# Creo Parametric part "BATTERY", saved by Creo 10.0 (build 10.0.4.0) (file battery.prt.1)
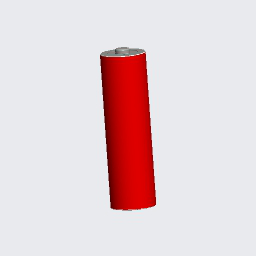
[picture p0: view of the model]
Units: millimeter Kilogram Sec (mmKs); MM, KILOGRAM, SECS

Created from: XX_SOLID_PART_MMKS_NEW_ABS.PRT

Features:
  1. datum plane "RIGHT"
  2. datum plane "TOP"
  3. datum plane "FRONT"
  4. coordinate system
  5. revolve "Revolve 1"

Surfaces: 12 torus, 6 cylinder, 5 plane, 2 cone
